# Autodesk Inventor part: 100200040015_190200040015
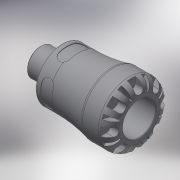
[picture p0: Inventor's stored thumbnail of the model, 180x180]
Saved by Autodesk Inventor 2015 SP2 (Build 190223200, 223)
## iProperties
Created: 2016-12
Part Number: 100200040015_190200040015
Material: Generic
Description: PLASSON MALE ADAPTOR 40X1.1/2" SERIES 1
Document SubType Name: Modeling
Designer: KIM
Mass: 447.839 g
Surface Area: 722.341 cm^2
Volume: 447.839 cm^3
Density: 1 g/cm^3
Appearance: Default
Author: KIM
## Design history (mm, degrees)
derived "1002.ipt"
feature "Solid1::1002.ipt"
tag "TaggingFeature1"
body "Solid1"
other parameters: "d0" = 106, "d1" = 30.66, "d6" = 73, "d8" = 59.5, "d13" = 8, "d14" = 8, "d15" = 0, "d17" = 360 deg, "d19" = 8 deg, "d20" = 0.8, "d21" = 0.8, "d22" = 8 deg, "d24" = 0, "d26" = 360 deg, "d32" = 0.925, "d33" = 7, "d34" = 47.803, "d35" = 5, "d38" = 21, "d39" = 1.43409, "d42" = 14, "d43" = 9.2, "d45" = 15.68, "d46" = 0, "d59" = 360 deg, "d61" = 11.9, "d62" = 0.8, "d64" = 0, "d65" = 0.7, "H_" = 106, "l_" = 73, "R_" = 47.803, "l_2" = 21, "d9" = 10
